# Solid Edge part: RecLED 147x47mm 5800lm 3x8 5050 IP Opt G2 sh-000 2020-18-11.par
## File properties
Author: radoslaw.kuczynski
Template: iso metric part.par
Last saved by: radoslaw.kuczynski
Revision: 1
Application: Solid Edge
Gęstość: 0,000 kg/m^3
Dokładność: 0,990
Username: radoslaw.kuczynski
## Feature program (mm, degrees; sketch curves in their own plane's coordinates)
body "unnamed Body 1"
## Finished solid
Body 1: solid body, 590 faces, 1500 edges, 931 vertices.
  Faces by surface: plane 335, cylinder 113, spline 80, cone 34, torus 11, sphere 10, spun 7
  Edges by curve: line 947, curve on surface 282, circle 161, ellipse 66, spline 38, intersection 6
Bounding box of the edges (mm; curved faces can reach further): 147.000 x 5.050 x 46.200, from (-73.7, -3.45, -23.1) to (73.3, 1.6, 23.1).
Cylindrical faces by radius (mm): R0.2 x39, R0.2002 x2, R0.2169 x3, R0.25 x12, R0.3 x2, R0.3373 x3, R0.4 x8, R0.4006 x2, R0.4008 x2, R0.525 x2, R0.6 x12, R1 x7, R1.0894 x2, R1.1 x14, R1.6 x2, R2 x1
Conical faces (half-angle, radius in mm at the cone's reference point): 0.5 deg R0.5056 x4, 0.5 deg R1.0082 x4, 1 deg R0.5511 x2, 10 deg R0.2132 x2, 10 deg R0.4132 x2, 18.4844 deg R1.0657 x4, 27.363 deg R0.6214 x2, 45 deg R0.575 x2, 45 deg R0.625 x4, 45 deg R3.2 x8
Toroidal faces (ring radius, tube radius in mm): R0.1 r0.2 x1, R0.8 r0.2 x4, R0.8522 r0.3 x2, R0.9002 r0.2 x1, R0.9018 r0.2 x1, R1.3 r0.2 x2
Spherical faces by radius (mm): R0.2 x8, R0.6 x2
Planar faces by outward normal: +x 37, +y 8, +z 33, -x 38, -y 68, -z 43, oblique 108
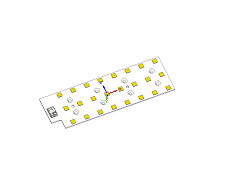
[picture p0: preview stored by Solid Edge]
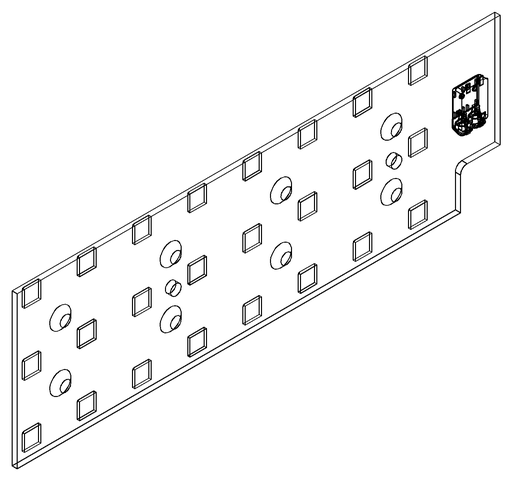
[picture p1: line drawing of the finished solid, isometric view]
